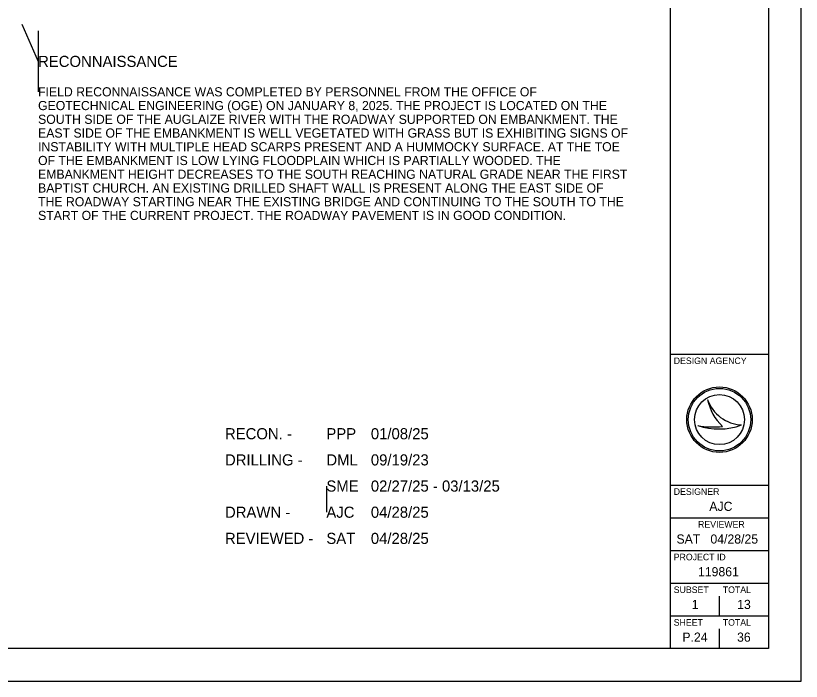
# Model space of a CAD drawing. Extents: x 0 to 34, y 0 to 22.
# Drawn here: x 21.99 to 34, y 0 to 10.18 of the extents above; entities that cross this region are included whole.
import ezdxf

# ---------------------------------------------------------------- set-up
doc = ezdxf.new("R2010")
doc.units = 0
for name, color, linetype in [('SC_Scratch1', 7, 'Continuous'), ('SH_Border', 7, 'Continuous'), ('SH_Cut_Line', 7, 'Continuous'), ('SH_Data', 7, 'Continuous'), ('SH_Text', 7, 'Continuous')]:
    doc.layers.add(name, color=color, linetype=linetype)

msp = doc.modelspace()

# ---------------------------------------------------------------- linework, layer by layer
at = {"layer": 'SC_Scratch1'}
for p, q in [((22.083, 10.047), (22.333, 9.477)), ((26.74, 2.985), (26.74, 2.585))]:
    msp.add_line(p, q, dxfattribs=at)
msp.add_lwpolyline([(22.333, 9.942), (22.333, 9.477), (22.333, 9.012)], dxfattribs=at)
at = {"layer": 'SH_Border'}
for p, q in [((32, 0.5), (32, 21.5)), ((32, 5), (33.5, 5)), ((32, 3), (33.5, 3)), ((32, 2.5), (33.5, 2.5)), ((32, 2), (33.5, 2)), ((32, 1.5), (33.5, 1.5)), ((32, 1), (33.5, 1))]:
    msp.add_line(p, q, dxfattribs=at)
msp.add_lwpolyline([(1.5, 21.5), (33.5, 21.5), (33.5, 0.5), (1.5, 0.5)], close=True, dxfattribs=at)
at = {"layer": 'SH_Cut_Line'}
msp.add_lwpolyline([(0, 0), (34, 0), (34, 22), (0, 22)], close=True, dxfattribs=at)
at = {"layer": 'SH_Data'}
for p, q in [((32.567, 4.31), (32.567, 4.31)), ((32.75, 4), (32.75, 4)), ((32.417, 3.91), (32.417, 3.91)), ((33.087, 3.919), (33.087, 3.919)), ((32.75, 1), (32.75, 1.3)), ((32.75, 0.5), (32.75, 0.8)), ((32.375, 0.675), (32.375, 0.675))]:
    msp.add_line(p, q, dxfattribs=at)
for radius in [0.5, 0.477, 0.477, 0.382]:
    msp.add_circle((32.75, 4), radius, dxfattribs=at)
for centre, radius, start, end in [((33.116, 4.498), 0.58, 198.9257, 198.9319), ((33.347, 4.47), 0.796, 191.6379, 191.6421), ((33.116, 4.498), 0.58, 198.9319, 267.1657), ((33.347, 4.47), 0.796, 191.6421, 226.0947), ((32.739, 4.87), 1.013, 251.4576, 290.0832), ((32.648, 5.154), 1.266, 259.4964, 259.4995), ((32.739, 4.87), 1.013, 251.4527, 251.4576), ((32.648, 5.154), 1.266, 259.4995, 276.6672)]:
    msp.add_arc(centre, radius, start, end, dxfattribs=at)

# ---------------------------------------------------------------- texts
for s, height, p in [('DESIGN AGENCY', 0.1, (32.05, 4.85)), ('DESIGNER', 0.1, (32.05, 2.85)), ('AJC', 0.14, (32.594, 2.605)), ('REVIEWER', 0.1, (32.422, 2.35)), ('SAT', 0.14, (32.092, 2.105)), ('04/28/25', 0.14, (32.611, 2.105)), ('PROJECT ID', 0.1, (32.05, 1.85)), ('SUBSET', 0.1, (32.05, 1.35)), ('TOTAL', 0.1, (32.8, 1.35)), ('1', 0.14, (32.325, 1.105)), ('13', 0.14, (33.02, 1.105)), ('SHEET', 0.1, (32.05, 0.85)), ('TOTAL', 0.1, (32.8, 0.85)), ('P.24', 0.14, (32.182, 0.605)), ('36', 0.14, (33.018, 0.605))]:
    msp.add_text(s, height=height, dxfattribs=at).set_placement(p)
at = {"layer": 'SH_Text'}
for s, height, p in [('RECONNAISSANCE', 0.17, (22.333, 9.392)), ('FIELD RECONNAISSANCE WAS COMPLETED BY PERSONNEL FROM THE OFFICE OF ', 0.14, (22.333, 8.942)), ('GEOTECHNICAL ENGINEERING (OGE) ON JANUARY 8, 2025. THE PROJECT IS LOCATED ON THE ', 0.14, (22.333, 8.732)), ('SOUTH SIDE OF THE AUGLAIZE RIVER WITH THE ROADWAY SUPPORTED ON EMBANKMENT. THE ', 0.14, (22.333, 8.522)), ('EAST SIDE OF THE EMBANKMENT IS WELL VEGETATED WITH GRASS BUT IS EXHIBITING SIGNS OF ', 0.14, (22.333, 8.312)), ('INSTABILITY WITH MULTIPLE HEAD SCARPS PRESENT AND A HUMMOCKY SURFACE. AT THE TOE ', 0.14, (22.333, 8.102)), ('OF THE EMBANKMENT IS LOW LYING FLOODPLAIN WHICH IS PARTIALLY WOODED. THE ', 0.14, (22.333, 7.892)), ('EMBANKMENT HEIGHT DECREASES TO THE SOUTH REACHING NATURAL GRADE NEAR THE FIRST ', 0.14, (22.333, 7.682)), ('BAPTIST CHURCH. AN EXISTING DRILLED SHAFT WALL IS PRESENT ALONG THE EAST SIDE OF ', 0.14, (22.333, 7.472)), ('THE ROADWAY STARTING NEAR THE EXISTING BRIDGE AND CONTINUING TO THE SOUTH TO THE ', 0.14, (22.333, 7.262)), ('START OF THE CURRENT PROJECT. THE ROADWAY PAVEMENT IS IN GOOD CONDITION. ', 0.14, (22.333, 7.052)), ('RECON. -', 0.17, (25.19, 3.7)), ('PPP', 0.17, (26.74, 3.7)), ('01/08/25', 0.17, (27.42, 3.7)), ('DRILLING -', 0.17, (25.19, 3.3)), ('DML', 0.17, (26.74, 3.3)), ('09/19/23', 0.17, (27.42, 3.3)), ('SME', 0.17, (26.74, 2.9)), ('02/27/25 - 03/13/25', 0.17, (27.42, 2.9)), ('DRAWN -', 0.17, (25.19, 2.5)), ('AJC', 0.17, (26.74, 2.5)), ('04/28/25', 0.17, (27.42, 2.5)), ('REVIEWED -', 0.17, (25.19, 2.1)), ('SAT', 0.17, (26.74, 2.1)), ('04/28/25', 0.17, (27.42, 2.1)), ('119861', 0.14, (32.421, 1.605))]:
    msp.add_text(s, height=height, dxfattribs=at).set_placement(p)

doc.saveas('drawing.dxf')
